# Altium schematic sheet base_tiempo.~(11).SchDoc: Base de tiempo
size A4; Revision: 1
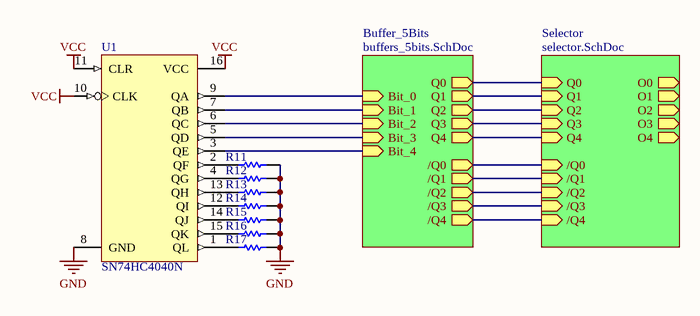
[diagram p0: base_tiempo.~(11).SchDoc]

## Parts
R11  Res Semi  [2012[0805]]  (value not drawn)
R12  Res Semi  [2012[0805]]  (value not drawn)
R13  Res Semi  [2012[0805]]  (value not drawn)
R14  Res Semi  [2012[0805]]  (value not drawn)
R15  Res Semi  [2012[0805]]  (value not drawn)
R16  Res Semi  [2012[0805]]  (value not drawn)
R17  Res Semi  [2012[0805]]  (value not drawn)
U1  SN74HC4040N  [N016]

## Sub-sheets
Buffer_5Bits = buffers_5bits.SchDoc: Bit_0 (in), Bit_1 (in), Bit_2 (in), Bit_3 (in), Bit_4 (in), Q0 (out), Q1 (out), Q2 (out), Q3 (out), Q4 (out), /Q0 (out), /Q1 (out), /Q2 (out), /Q3 (out), /Q4 (out)
Selector = selector.SchDoc: Q0 (in), Q1 (in), Q2 (in), Q3 (in), Q4 (in), /Q0 (in), /Q1 (in), /Q2 (in), /Q3 (in), /Q4 (in), O0 (out), O1 (out), O2 (out), O3 (out), O4 (out)

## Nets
GND: R11.2 R12.2 R13.2 R14.2 R15.2 R16.2 R17.2 U1.8(GND)
VCC: U1.10(CLK) U1.11(CLR) U1.16(VCC)
NetR11_1: R11.1 U1.2(QF)
NetR12_1: R12.1 U1.4(QG)
NetR13_1: R13.1 U1.13(QH)
NetR14_1: R14.1 U1.12(QI)
NetR15_1: R15.1 U1.14(QJ)
NetR16_1: R16.1 U1.15(QK)
NetR17_1: R17.1 U1.1(QL)
NetU1_3: U1.3(QE) ; sheet Buffer_5Bits/Bit_4
NetU1_5: U1.5(QD) ; sheet Buffer_5Bits/Bit_3
NetU1_6: U1.6(QC) ; sheet Buffer_5Bits/Bit_2
NetU1_7: U1.7(QB) ; sheet Buffer_5Bits/Bit_1
NetU1_9: U1.9(QA) ; sheet Buffer_5Bits/Bit_0
(unnamed): sheet Buffer_5Bits/Q0, sheet Selector/Q0
(unnamed): sheet Buffer_5Bits/Q1, sheet Selector/Q1  [a separate net that carries the same name]
(unnamed): sheet Buffer_5Bits/Q2, sheet Selector/Q2  [a separate net that carries the same name]
(unnamed): sheet Buffer_5Bits/Q3, sheet Selector/Q3  [a separate net that carries the same name]
(unnamed): sheet Buffer_5Bits/Q4, sheet Selector/Q4  [a separate net that carries the same name]
(unnamed): sheet Buffer_5Bits//Q0, sheet Selector//Q0  [a separate net that carries the same name]
(unnamed): sheet Buffer_5Bits//Q1, sheet Selector//Q1  [a separate net that carries the same name]
(unnamed): sheet Buffer_5Bits//Q2, sheet Selector//Q2  [a separate net that carries the same name]
(unnamed): sheet Buffer_5Bits//Q3, sheet Selector//Q3  [a separate net that carries the same name]
(unnamed): sheet Buffer_5Bits//Q4, sheet Selector//Q4  [a separate net that carries the same name]

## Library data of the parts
R11-R17 = Res Semi: Semiconductor Resistor; Value: 1K
U1 = SN74HC4040N: 12-Bit Asynchronous Binary Counter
